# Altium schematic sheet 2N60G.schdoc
size 127 x 101 mm
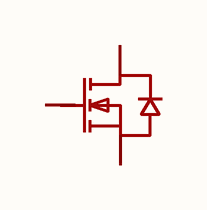
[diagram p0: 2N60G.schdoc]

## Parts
Q?  2n60g  [SOT-223-3_L6.5-W3.4-P2.30-LS7.0-BR-1]  (value not drawn)

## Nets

Not connected (* = marked no-connect by the designer): Q? 1(G) 2(D) 3(S)

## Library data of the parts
Q? = 2n60g: 数量:1个N沟道;漏源电压(Vdss):600V;连续漏极电流(Id):2A;导通电阻(RDS(on)):4.2Ω@10V;耗散功率(Pd):-;阈值电压(Vgs(th)):4V@250uA;; Manufacturer: UMW(友台半导体); AddInBom: yes; ModelId: 0a360ebfdb9248a182f670f5fd8a68d2; ModelTransform: 275.59,255.905,0,0,0,0,-3.937,0,0; Number: 1个N沟道; Drain to Source Voltage: 600V; Current - Continuous Drain(Id): 2A; Gate Charge(Qg): 7.2nC@10V; Input Capacitance(Ciss): 320pF; Type: N沟道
